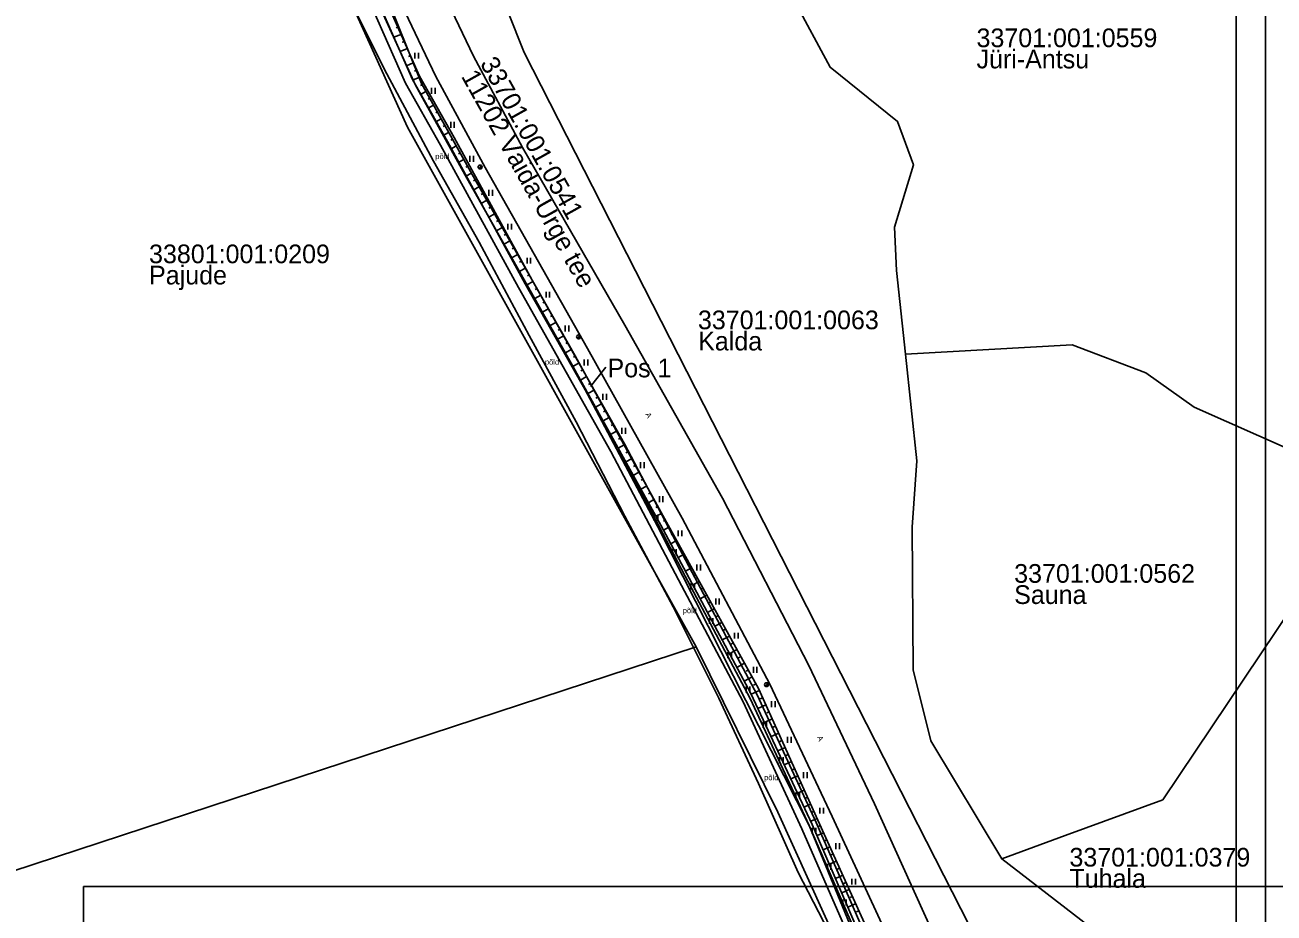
# Model space of a CAD drawing. Extents: x 554947 to 555436, y 6564938 to 6565792.
# Drawn here: x 555027.7 to 555187.9, y 6565441.5 to 6565555.5 of the extents above; entities that cross this region are included whole.
import ezdxf

# ---------------------------------------------------------------- set-up
doc = ezdxf.new("R2010")
doc.units = 0
for name, color, linetype in [('HALJASTUS', 7, 'Continuous'), ('KASUTUSALA', 7, 'Continuous'), ('KPKAABEL', 7, 'Continuous'), ('PIIR', 7, 'Continuous'), ('POST', 7, 'Continuous'), ('PR_SIDE', 7, 'Continuous'), ('RELJEEF', 7, 'Continuous'), ('TEE', 7, 'Continuous'), ('VORMISTUS_1', 7, 'Continuous'), ('VORMISTUS_2', 7, 'Continuous'), ('VORMISTUS_3', 7, 'Continuous')]:
    doc.layers.add(name, color=color, linetype=linetype)

msp = doc.modelspace()

# ---------------------------------------------------------------- linework, layer by layer
at = {"layer": 'HALJASTUS'}
for p, q in [((555077.72, 6565551.92), (555077.72, 6565551.16)), ((555078.18, 6565551.92), (555078.18, 6565551.16)), ((555079.87, 6565547.41), (555079.87, 6565546.65)), ((555080.32, 6565547.41), (555080.32, 6565546.65)), ((555082.32, 6565543.05), (555082.32, 6565542.29)), ((555082.77, 6565543.05), (555082.77, 6565542.29)), ((555084.77, 6565538.69), (555084.77, 6565537.93)), ((555085.22, 6565538.69), (555085.22, 6565537.93)), ((555087.21, 6565534.33), (555087.21, 6565533.57)), ((555087.67, 6565534.33), (555087.67, 6565533.57)), ((555089.66, 6565529.97), (555089.66, 6565529.21)), ((555090.12, 6565529.97), (555090.12, 6565529.21)), ((555092.11, 6565525.61), (555092.11, 6565524.85)), ((555092.57, 6565525.61), (555092.57, 6565524.85)), ((555094.56, 6565521.25), (555094.56, 6565520.49)), ((555095.01, 6565521.25), (555095.01, 6565520.49)), ((555097.01, 6565516.89), (555097.01, 6565516.13)), ((555097.46, 6565516.89), (555097.46, 6565516.13)), ((555099.44, 6565512.53), (555099.44, 6565511.76)), ((555099.9, 6565512.53), (555099.9, 6565511.76)), ((555101.85, 6565508.14), (555101.85, 6565507.38)), ((555102.31, 6565508.14), (555102.31, 6565507.38)), ((555104.27, 6565503.76), (555104.27, 6565503)), ((555104.72, 6565503.76), (555104.72, 6565503)), ((555106.68, 6565499.38), (555106.68, 6565498.62)), ((555107.13, 6565499.38), (555107.13, 6565498.62)), ((555109.09, 6565495), (555109.09, 6565494.24)), ((555109.54, 6565495), (555109.54, 6565494.24)), ((555108.42, 6565492.59), (555108.42, 6565491.83)), ((555108.87, 6565492.59), (555108.87, 6565491.83)), ((555111.5, 6565490.62), (555111.5, 6565489.86)), ((555111.95, 6565490.62), (555111.95, 6565489.86)), ((555110.78, 6565488.19), (555110.78, 6565487.43)), ((555111.24, 6565488.19), (555111.24, 6565487.43)), ((555113.91, 6565486.24), (555113.91, 6565485.48)), ((555114.36, 6565486.24), (555114.36, 6565485.48)), ((555113.14, 6565483.78), (555113.14, 6565483.02)), ((555113.6, 6565483.78), (555113.6, 6565483.02)), ((555116.32, 6565481.86), (555116.32, 6565481.1)), ((555116.77, 6565481.86), (555116.77, 6565481.1)), ((555115.51, 6565479.37), (555115.51, 6565478.61)), ((555115.96, 6565479.37), (555115.96, 6565478.61)), ((555118.73, 6565477.48), (555118.73, 6565476.72)), ((555119.18, 6565477.48), (555119.18, 6565476.72)), ((555117.87, 6565474.97), (555117.87, 6565474.21)), ((555118.32, 6565474.97), (555118.32, 6565474.21)), ((555121.14, 6565473.1), (555121.14, 6565472.34)), ((555121.6, 6565473.1), (555121.6, 6565472.34)), ((555120.23, 6565470.56), (555120.23, 6565469.8)), ((555120.69, 6565470.56), (555120.69, 6565469.8)), ((555123.46, 6565468.68), (555123.46, 6565467.92)), ((555123.92, 6565468.68), (555123.92, 6565467.92)), ((555122.38, 6565466.05), (555122.38, 6565465.28)), ((555122.83, 6565466.05), (555122.83, 6565465.28)), ((555125.53, 6565464.12), (555125.53, 6565463.36)), ((555125.98, 6565464.12), (555125.98, 6565463.36)), ((555124.5, 6565461.52), (555124.5, 6565460.76)), ((555124.95, 6565461.52), (555124.95, 6565460.76)), ((555127.59, 6565459.57), (555127.59, 6565458.81)), ((555128.05, 6565459.57), (555128.05, 6565458.81)), ((555126.61, 6565456.99), (555126.61, 6565456.23)), ((555127.07, 6565456.99), (555127.07, 6565456.23)), ((555129.66, 6565455.02), (555129.66, 6565454.26)), ((555130.12, 6565455.02), (555130.12, 6565454.26)), ((555128.68, 6565452.44), (555128.68, 6565451.67)), ((555129.14, 6565452.44), (555129.14, 6565451.67)), ((555131.73, 6565450.46), (555131.73, 6565449.7)), ((555132.18, 6565450.46), (555132.18, 6565449.7)), ((555130.64, 6565447.83), (555130.64, 6565447.07)), ((555131.09, 6565447.83), (555131.09, 6565447.07)), ((555133.79, 6565445.91), (555133.79, 6565445.15)), ((555134.25, 6565445.91), (555134.25, 6565445.15)), ((555132.6, 6565443.23), (555132.6, 6565442.47)), ((555133.05, 6565443.23), (555133.05, 6565442.47))]:
    msp.add_line(p, q, dxfattribs=at)
msp.add_lwpolyline([(555097.58, 6565512.39), (555108.86, 6565491.15), (555128.28, 6565452.72), (555137.76, 6565429.75), (555137.45, 6565422.91)], dxfattribs=at)
at = {"layer": 'KASUTUSALA'}
for points in [[(555135.79, 6565433.02), (555127.37, 6565452.31), (555119.84, 6565468.62), (555111.52, 6565484.26), (555102.86, 6565500.76), (555091.01, 6565521.78), (555081.02, 6565540.05), (555076.53, 6565548.03), (555070.06, 6565562.68)], [(555071.91, 6565563.44), (555078.32, 6565548.93), (555082.77, 6565541.02), (555092.76, 6565522.75), (555104.62, 6565501.72), (555113.29, 6565485.19), (555121.64, 6565469.51), (555129.19, 6565453.13), (555137.61, 6565433.85)]]:
    msp.add_lwpolyline(points, dxfattribs=at)
at = {"layer": 'KPKAABEL'}
msp.add_lwpolyline([(555022.08, 6565654.91), (555021.62, 6565652.63), (555021.53, 6565649.77), (555022.79, 6565647.23), (555026.48, 6565641.46), (555030.61, 6565629.73), (555035.38, 6565618.81), (555040.84, 6565608.06), (555047.09, 6565597.8), (555053.57, 6565587.29), (555056.07, 6565583.7), (555062.11, 6565572.67), (555068.25, 6565560.98), (555073.77, 6565549.85), (555080.11, 6565537.98), (555085.96, 6565527.61), (555092.4, 6565515.61), (555098.4, 6565504.54), (555104.64, 6565492.44), (555110.84, 6565480.82), (555116.7, 6565469.07), (555121.82, 6565458.12), (555126.89, 6565446.73), (555132.74, 6565435.39)], dxfattribs=at)
at = {"layer": 'PIIR'}
for points in [[(555016.05, 6565654.91), (555030.24, 6565648.23), (555043.11, 6565640.11), (555053.62, 6565632.14), (555056.61, 6565622.91), (555057.22, 6565600.73), (555060.42, 6565583.26), (555065.78, 6565566.7), (555076.76, 6565542.38), (555113.82, 6565475.68), (554946.63, 6565420.78), (554981.01, 6565316.76), (555160.07, 6565375.54), (555166.64, 6565360.5), (555167.67, 6565357.91)], [(555144.16, 6565410.6), (555124.27, 6565454.45), (555113.82, 6565475.68), (555076.76, 6565542.38), (555065.78, 6565566.7), (555060.42, 6565583.26), (555057.22, 6565600.73), (555056.61, 6565622.91), (555063.43, 6565647.29), (555114.24, 6565634), (555129.77, 6565611.2), (555130.73, 6565621.32), (555138.66, 6565615.26), (555160.12, 6565598.86), (555193.24, 6565604.68), (555193.7, 6565602.7), (555225.47, 6565605.89), (555234.35, 6565605.6), (555251.24, 6565598.48), (555330.71, 6565538.85), (555343.81, 6565536.56), (555350.68, 6565540.44), (555361.56, 6565549.57), (555393.07, 6565582.1)], [(555171.91, 6565394.64), (555091.74, 6565551.94), (555075.34, 6565593.24), (555074.13, 6565607.82), (555079.04, 6565618.4), (555093.56, 6565628.47), (555109.96, 6565624.83), (555116.17, 6565610.5), (555099.5, 6565594.91), (555105.26, 6565587.71), (555119.63, 6565564.84), (555126.35, 6565558.74), (555131.01, 6565550.06), (555139.64, 6565543.1), (555141.68, 6565537.52), (555139.26, 6565529.51), (555139.49, 6565523.98), (555140.65, 6565513.25), (555142.13, 6565499.56), (555141.53, 6565491.02), (555141.65, 6565472.71), (555143.93, 6565463.6), (555153.01, 6565448.47), (555207.22, 6565406.57)], [(555393.07, 6565560.97), (555353.12, 6565523.87), (555343.14, 6565512.46), (555302.6, 6565539.71), (555242.37, 6565583.94), (555179.42, 6565586.32), (555138.98, 6565580.6), (555121.18, 6565602.26), (555116.17, 6565610.5), (555109.96, 6565624.83), (555093.56, 6565628.47), (555079.04, 6565618.4), (555074.13, 6565607.82), (555075.34, 6565593.24), (555091.74, 6565551.94), (555171.91, 6565394.64), (555191.35, 6565341.19), (555195.08, 6565294.61), (555195.28, 6565271.63), (555191.64, 6565237.48)]]:
    msp.add_lwpolyline(points, dxfattribs=at)
for points in [[(555121.18, 6565602.26), (555138.98, 6565580.6), (555179.42, 6565586.32), (555242.37, 6565583.94), (555302.6, 6565539.71), (555287.77, 6565518.56), (555207.29, 6565506.14), (555200.64, 6565496.23), (555185.97, 6565502.75), (555177.68, 6565506.44), (555171.49, 6565510.85), (555162.05, 6565514.45), (555140.65, 6565513.25), (555139.49, 6565523.98), (555139.26, 6565529.51), (555141.68, 6565537.52), (555139.64, 6565543.1), (555131.01, 6565550.06), (555126.35, 6565558.74), (555119.63, 6565564.84), (555105.26, 6565587.71), (555099.5, 6565594.91), (555116.17, 6565610.5)], [(555153.01, 6565448.47), (555161.15, 6565451.45), (555173.66, 6565456.03), (555207.29, 6565506.14), (555287.77, 6565518.56), (555302.6, 6565539.71), (555343.14, 6565512.46), (555319.44, 6565481.04), (555323.07, 6565461.26), (555312.9, 6565433.84), (555316.84, 6565372.52), (555318.72, 6565342.57), (555320.51, 6565314.61), (555303.13, 6565302.54), (555208.78, 6565303.3), (555205.15, 6565297.11), (555200.72, 6565310.3), (555206.9, 6565339.44), (555221.23, 6565376.06), (555216.83, 6565392.35), (555207.22, 6565406.57)], [(555140.65, 6565513.25), (555162.05, 6565514.45), (555171.49, 6565510.85), (555177.68, 6565506.44), (555185.97, 6565502.75), (555200.64, 6565496.23), (555173.66, 6565456.03), (555161.15, 6565451.45), (555153.01, 6565448.47), (555143.93, 6565463.6), (555141.65, 6565472.71), (555141.53, 6565491.02), (555142.13, 6565499.56)], [(554981.01, 6565316.76), (554946.63, 6565420.78), (555113.82, 6565475.68), (555124.27, 6565454.45), (555144.16, 6565410.6), (555160.07, 6565375.54)]]:
    msp.add_lwpolyline(points, close=True, dxfattribs=at)
at = {"layer": 'POST'}
for p, q in [((555085.91, 6565537.07), (555086.26, 6565537.43)), ((555098.55, 6565515.27), (555098.9, 6565515.62)), ((555122.66, 6565470.63), (555123.01, 6565470.98))]:
    msp.add_line(p, q, dxfattribs=at)
for centre in [(555086.09, 6565537.25), (555098.72, 6565515.45), (555122.83, 6565470.81)]:
    msp.add_circle(centre, 0.25, dxfattribs=at)
for centre, radius, start, end in [((555086.09, 6565537.25), 0.225, 224.8541, 45.0356), ((555086.09, 6565537.25), 0.2, 224.8427, 45.047), ((555086.09, 6565537.25), 0.175, 224.8281, 45.0616), ((555086.09, 6565537.25), 0.15, 224.8087, 45.081), ((555086.09, 6565537.25), 0.125, 224.7814, 45.1083), ((555086.09, 6565537.25), 0.1, 224.7406, 45.1491), ((555086.09, 6565537.25), 0.075, 224.6725, 45.2172), ((555086.09, 6565537.25), 0.05, 224.5363, 45.3534), ((555086.09, 6565537.25), 0.025, 224.1278, 45.7619), ((555098.72, 6565515.45), 0.225, 224.8541, 45.0356), ((555098.72, 6565515.45), 0.2, 224.8427, 45.047), ((555098.72, 6565515.45), 0.175, 224.8281, 45.0616), ((555098.72, 6565515.45), 0.15, 224.8087, 45.081), ((555098.72, 6565515.45), 0.125, 224.7814, 45.1083), ((555098.72, 6565515.45), 0.1, 224.7406, 45.1491), ((555098.72, 6565515.45), 0.075, 224.6725, 45.2172), ((555098.72, 6565515.45), 0.05, 224.5363, 45.3534), ((555098.72, 6565515.45), 0.025, 224.1278, 45.7619), ((555122.83, 6565470.81), 0.225, 224.8541, 45.0356), ((555122.83, 6565470.81), 0.2, 224.8427, 45.047), ((555122.83, 6565470.81), 0.175, 224.8281, 45.0616), ((555122.83, 6565470.81), 0.15, 224.8087, 45.081), ((555122.83, 6565470.81), 0.125, 224.7814, 45.1083), ((555122.83, 6565470.81), 0.1, 224.7406, 45.1491), ((555122.83, 6565470.81), 0.075, 224.6725, 45.2172), ((555122.83, 6565470.81), 0.05, 224.5363, 45.3534), ((555122.83, 6565470.81), 0.025, 224.1278, 45.7619)]:
    msp.add_arc(centre, radius, start, end, dxfattribs=at)
at = {"layer": 'PR_SIDE'}
msp.add_lwpolyline([(555136.7, 6565433.44), (555128.28, 6565452.72), (555120.74, 6565469.06), (555112.41, 6565484.72), (555103.74, 6565501.24), (555091.88, 6565522.26), (555081.89, 6565540.54), (555077.43, 6565548.48), (555070.99, 6565563.06), (555062.87, 6565584.51), (555061.06, 6565592.84), (555060.38, 6565594.02), (555051.55, 6565599.57), (555040.59, 6565606.01), (555035.25, 6565616.95), (555028.14, 6565630.97), (555028.18, 6565632.46), (555043.56, 6565658.77)], dxfattribs=at)
at = {"layer": 'RELJEEF'}
for p, q in [((555076.04, 6565554.31), (555075, 6565553.9)), ((555075.66, 6565555.24), (555075.34, 6565555.11)), ((555076.41, 6565553.38), (555076.11, 6565553.26)), ((555076.78, 6565552.45), (555075.83, 6565552.08)), ((555077.15, 6565551.53), (555076.88, 6565551.42)), ((555077.52, 6565550.6), (555076.66, 6565550.25)), ((555077.89, 6565549.67), (555077.65, 6565549.57)), ((555078.27, 6565548.74), (555077.49, 6565548.43)), ((555078.66, 6565547.82), (555078.45, 6565547.71)), ((555079.14, 6565546.95), (555078.45, 6565546.57)), ((555079.63, 6565546.07), (555079.42, 6565545.96)), ((555080.11, 6565545.2), (555079.42, 6565544.81)), ((555080.6, 6565544.33), (555080.39, 6565544.21)), ((555081.08, 6565543.45), (555080.39, 6565543.06)), ((555082.05, 6565541.7), (555081.35, 6565541.31)), ((555081.57, 6565542.58), (555081.36, 6565542.46)), ((555083.02, 6565539.95), (555082.32, 6565539.56)), ((555082.54, 6565540.83), (555082.33, 6565540.71)), ((555083.51, 6565539.08), (555083.3, 6565538.96)), ((555084, 6565538.2), (555083.29, 6565537.81)), ((555084.48, 6565537.33), (555084.27, 6565537.21)), ((555084.97, 6565536.46), (555084.26, 6565536.06)), ((555085.46, 6565535.59), (555085.25, 6565535.46)), ((555085.95, 6565534.72), (555085.24, 6565534.31)), ((555086.45, 6565533.85), (555086.23, 6565533.72)), ((555086.94, 6565532.98), (555086.22, 6565532.57)), ((555087.44, 6565532.11), (555087.22, 6565531.98)), ((555087.93, 6565531.24), (555087.2, 6565530.82)), ((555088.42, 6565530.37), (555088.2, 6565530.24)), ((555088.92, 6565529.5), (555088.18, 6565529.08)), ((555089.91, 6565527.76), (555089.16, 6565527.34)), ((555089.41, 6565528.63), (555089.19, 6565528.51)), ((555090.9, 6565526.02), (555090.14, 6565525.6)), ((555090.4, 6565526.89), (555090.18, 6565526.77)), ((555091.88, 6565524.29), (555091.13, 6565523.85)), ((555091.39, 6565525.15), (555091.16, 6565525.03)), ((555092.87, 6565522.55), (555092.11, 6565522.11)), ((555092.38, 6565523.42), (555092.15, 6565523.29)), ((555093.86, 6565520.81), (555093.09, 6565520.37)), ((555093.37, 6565521.68), (555093.14, 6565521.55)), ((555094.85, 6565519.07), (555094.07, 6565518.62)), ((555094.36, 6565519.94), (555094.12, 6565519.81)), ((555095.35, 6565518.2), (555095.11, 6565518.07)), ((555095.84, 6565517.33), (555095.05, 6565516.88)), ((555096.33, 6565516.46), (555096.1, 6565516.33)), ((555096.83, 6565515.59), (555096.03, 6565515.14)), ((555097.32, 6565514.72), (555097.08, 6565514.59)), ((555097.82, 6565513.85), (555097.01, 6565513.4)), ((555098.31, 6565512.98), (555098.07, 6565512.85)), ((555098.79, 6565512.11), (555097.98, 6565511.66)), ((555099.27, 6565511.23), (555099.03, 6565511.1)), ((555099.75, 6565510.35), (555098.95, 6565509.91)), ((555100.23, 6565509.47), (555099.99, 6565509.34)), ((555100.71, 6565508.6), (555099.92, 6565508.17)), ((555101.67, 6565506.84), (555100.89, 6565506.42)), ((555101.19, 6565507.72), (555100.95, 6565507.59)), ((555102.63, 6565505.09), (555101.86, 6565504.67)), ((555102.15, 6565505.96), (555101.92, 6565505.84)), ((555103.59, 6565503.33), (555102.83, 6565502.92)), ((555103.11, 6565504.21), (555102.88, 6565504.08)), ((555104.55, 6565501.58), (555103.8, 6565501.17)), ((555104.07, 6565502.46), (555103.84, 6565502.33)), ((555105.51, 6565499.82), (555104.77, 6565499.42)), ((555105.03, 6565500.7), (555104.8, 6565500.58)), ((555105.99, 6565498.95), (555105.77, 6565498.83)), ((555106.47, 6565498.07), (555105.74, 6565497.67)), ((555106.95, 6565497.19), (555106.73, 6565497.07)), ((555107.43, 6565496.31), (555106.71, 6565495.92)), ((555107.91, 6565495.44), (555107.69, 6565495.32)), ((555108.38, 6565494.56), (555107.68, 6565494.17)), ((555108.86, 6565493.68), (555108.65, 6565493.57)), ((555109.34, 6565492.8), (555108.65, 6565492.42)), ((555109.82, 6565491.93), (555109.62, 6565491.81)), ((555110.31, 6565491.05), (555109.61, 6565490.66)), ((555111.28, 6565489.3), (555110.55, 6565488.9)), ((555110.79, 6565490.18), (555110.58, 6565490.06)), ((555112.25, 6565487.55), (555111.5, 6565487.14)), ((555111.76, 6565488.43), (555111.54, 6565488.3)), ((555113.22, 6565485.81), (555112.44, 6565485.37)), ((555112.73, 6565486.68), (555112.5, 6565486.55)), ((555114.19, 6565484.06), (555113.38, 6565483.61)), ((555113.71, 6565484.93), (555113.47, 6565484.8)), ((555115.16, 6565482.31), (555114.33, 6565481.84)), ((555114.68, 6565483.18), (555114.43, 6565483.05)), ((555115.65, 6565481.43), (555115.39, 6565481.29)), ((555116.13, 6565480.56), (555115.27, 6565480.08)), ((555116.62, 6565479.68), (555116.35, 6565479.54)), ((555117.1, 6565478.81), (555116.21, 6565478.32)), ((555117.59, 6565477.94), (555117.32, 6565477.79)), ((555118.07, 6565477.06), (555117.15, 6565476.55)), ((555118.56, 6565476.19), (555118.28, 6565476.03)), ((555119.04, 6565475.31), (555118.1, 6565474.79)), ((555119.53, 6565474.44), (555119.24, 6565474.28)), ((555120.02, 6565473.56), (555119.04, 6565473.02)), ((555120.5, 6565472.69), (555120.2, 6565472.53)), ((555120.99, 6565471.82), (555119.98, 6565471.26)), ((555121.93, 6565470.06), (555120.87, 6565469.58)), ((555121.47, 6565470.94), (555121.17, 6565470.77)), ((555122.75, 6565468.23), (555121.72, 6565467.77)), ((555122.34, 6565469.14), (555122.03, 6565469)), ((555123.57, 6565466.41), (555122.57, 6565465.96)), ((555123.16, 6565467.32), (555122.86, 6565467.18)), ((555124.39, 6565464.58), (555123.42, 6565464.15)), ((555123.98, 6565465.5), (555123.69, 6565465.36)), ((555124.8, 6565463.67), (555124.52, 6565463.54)), ((555125.21, 6565462.76), (555124.27, 6565462.33)), ((555125.62, 6565461.85), (555125.34, 6565461.72)), ((555126.03, 6565460.94), (555125.11, 6565460.52)), ((555126.44, 6565460.02), (555126.17, 6565459.9)), ((555126.85, 6565459.11), (555125.96, 6565458.71)), ((555127.26, 6565458.2), (555127, 6565458.08)), ((555127.67, 6565457.29), (555126.81, 6565456.9)), ((555128.49, 6565455.46), (555127.66, 6565455.09)), ((555128.08, 6565456.37), (555127.83, 6565456.26)), ((555129.31, 6565453.64), (555128.51, 6565453.28)), ((555128.9, 6565454.55), (555128.66, 6565454.44)), ((555130.14, 6565451.82), (555129.31, 6565451.44)), ((555129.72, 6565452.73), (555129.48, 6565452.62)), ((555130.55, 6565450.9), (555130.3, 6565450.79)), ((555130.96, 6565449.99), (555130.1, 6565449.61)), ((555131.37, 6565449.08), (555131.11, 6565448.96)), ((555131.78, 6565448.17), (555130.9, 6565447.77)), ((555132.2, 6565447.26), (555131.92, 6565447.14)), ((555132.61, 6565446.35), (555131.69, 6565445.93)), ((555133.02, 6565445.44), (555132.74, 6565445.31)), ((555133.43, 6565444.53), (555132.48, 6565444.09)), ((555134.26, 6565442.7), (555133.27, 6565442.26)), ((555133.84, 6565443.62), (555133.55, 6565443.48)), ((555134.67, 6565441.79), (555134.37, 6565441.66))]:
    msp.add_line(p, q, dxfattribs=at)
for points in [[(555061.19, 6565603.86), (555063.02, 6565596.51), (555064.38, 6565585.09), (555067.44, 6565575.67), (555073.66, 6565560.25), (555078.57, 6565547.98), (555085.07, 6565536.27), (555098.29, 6565513.03), (555109.98, 6565491.65), (555121.81, 6565470.32), (555129.41, 6565453.42), (555139.71, 6565430.65), (555142.38, 6565424.28), (555142.55, 6565422.18)], [(555061.19, 6565603.86), (555061.85, 6565596.37), (555062.87, 6565584.51), (555066.18, 6565575.08), (555072.1, 6565560.27), (555077.8, 6565547.74), (555084.38, 6565535.83), (555097.58, 6565512.39), (555109.29, 6565491.27), (555120.83, 6565469.69), (555128.7, 6565452.87), (555138.48, 6565430.17), (555141.35, 6565423.96), (555142.55, 6565422.18)]]:
    msp.add_lwpolyline(points, dxfattribs=at)
at = {"layer": 'TEE'}
for points in [[(555063.04, 6565604.03), (555063.89, 6565596.59), (555066.15, 6565585.55), (555068.84, 6565576.18), (555074.68, 6565560.94), (555080.39, 6565548.87), (555086.72, 6565537.19), (555099.86, 6565513.95), (555112, 6565492.2), (555123.27, 6565470.87), (555131.27, 6565453.89), (555141.63, 6565431.43)], [(555146.7, 6565433.42), (555136.69, 6565455.53), (555128.27, 6565473.28), (555117.19, 6565494.73), (555104.65, 6565516.95), (555091.54, 6565539.74), (555085.22, 6565551.47), (555079.65, 6565563.24), (555074, 6565577.71), (555071.34, 6565586.86), (555069.39, 6565597.54), (555068.63, 6565604.43)]]:
    msp.add_lwpolyline(points, dxfattribs=at)
at = {"layer": 'VORMISTUS_1'}
msp.add_lwpolyline([(555035.19, 6565444.91), (555245.19, 6565444.91), (555245.19, 6565147.91), (555035.19, 6565147.91)], close=True, dxfattribs=at)
at = {"layer": 'VORMISTUS_2'}
msp.add_line((555100.25, 6565509.08), (555102.2, 6565511.58), dxfattribs=at)
msp.add_lwpolyline([(555186.86, 6565394.91), (555021.86, 6565394.91), (555021.86, 6565604.91), (555186.86, 6565604.91)], close=True, dxfattribs=at)
at = {"layer": 'VORMISTUS_3'}
msp.add_lwpolyline([(555183.07, 6565701.75), (555393.07, 6565701.75), (555393.07, 6565404.75), (555183.07, 6565404.75)], close=True, dxfattribs=at)

# ---------------------------------------------------------------- texts
at = {"layer": 'HALJASTUS'}
for p in [(555080.34, 6565538.27), (555094.4, 6565511.88), (555112.08, 6565479.98), (555122.52, 6565458.55)]:
    msp.add_text('põld', height=0.7, rotation=359.9544, dxfattribs=at).set_placement(p)
at = {"layer": 'PIIR'}
for s, p in [('33701:001:0559', (555149.77, 6565552.63)), ('Jüri-Antsu', (555149.77, 6565549.91)), ('33801:001:0209', (555043.62, 6565524.9)), ('Pajude', (555043.62, 6565522.18)), ('33701:001:0063', (555114.03, 6565516.43)), ('Kalda', (555114.06, 6565513.71)), ('33701:001:0562', (555154.6, 6565483.89)), ('Sauna', (555154.6, 6565481.17)), ('33701:001:0379', (555161.69, 6565447.47)), ('Tuhala', (555161.69, 6565444.75))]:
    msp.add_text(s, height=2.4, dxfattribs=at).set_placement(p)
for s, p in [('33701:001:0541', (555086.02, 6565550.55)), ('11202 Vaida-Urge tee', (555083.6, 6565548.9))]:
    msp.add_text(s, height=2.4, rotation=299.2738, dxfattribs=at).set_placement(p)
at = {"layer": 'TEE'}
for rotation, p in [(299.9634, (555107.26, 6565505.5)), (292.7913, (555129.3, 6565464.07))]:
    msp.add_text('A', height=0.7, rotation=rotation, dxfattribs=at).set_placement(p)
at = {"layer": 'VORMISTUS_2'}
msp.add_text('Pos 1', height=2.4, dxfattribs=at).set_placement((555102.43, 6565510.26))

doc.saveas('drawing.dxf')
